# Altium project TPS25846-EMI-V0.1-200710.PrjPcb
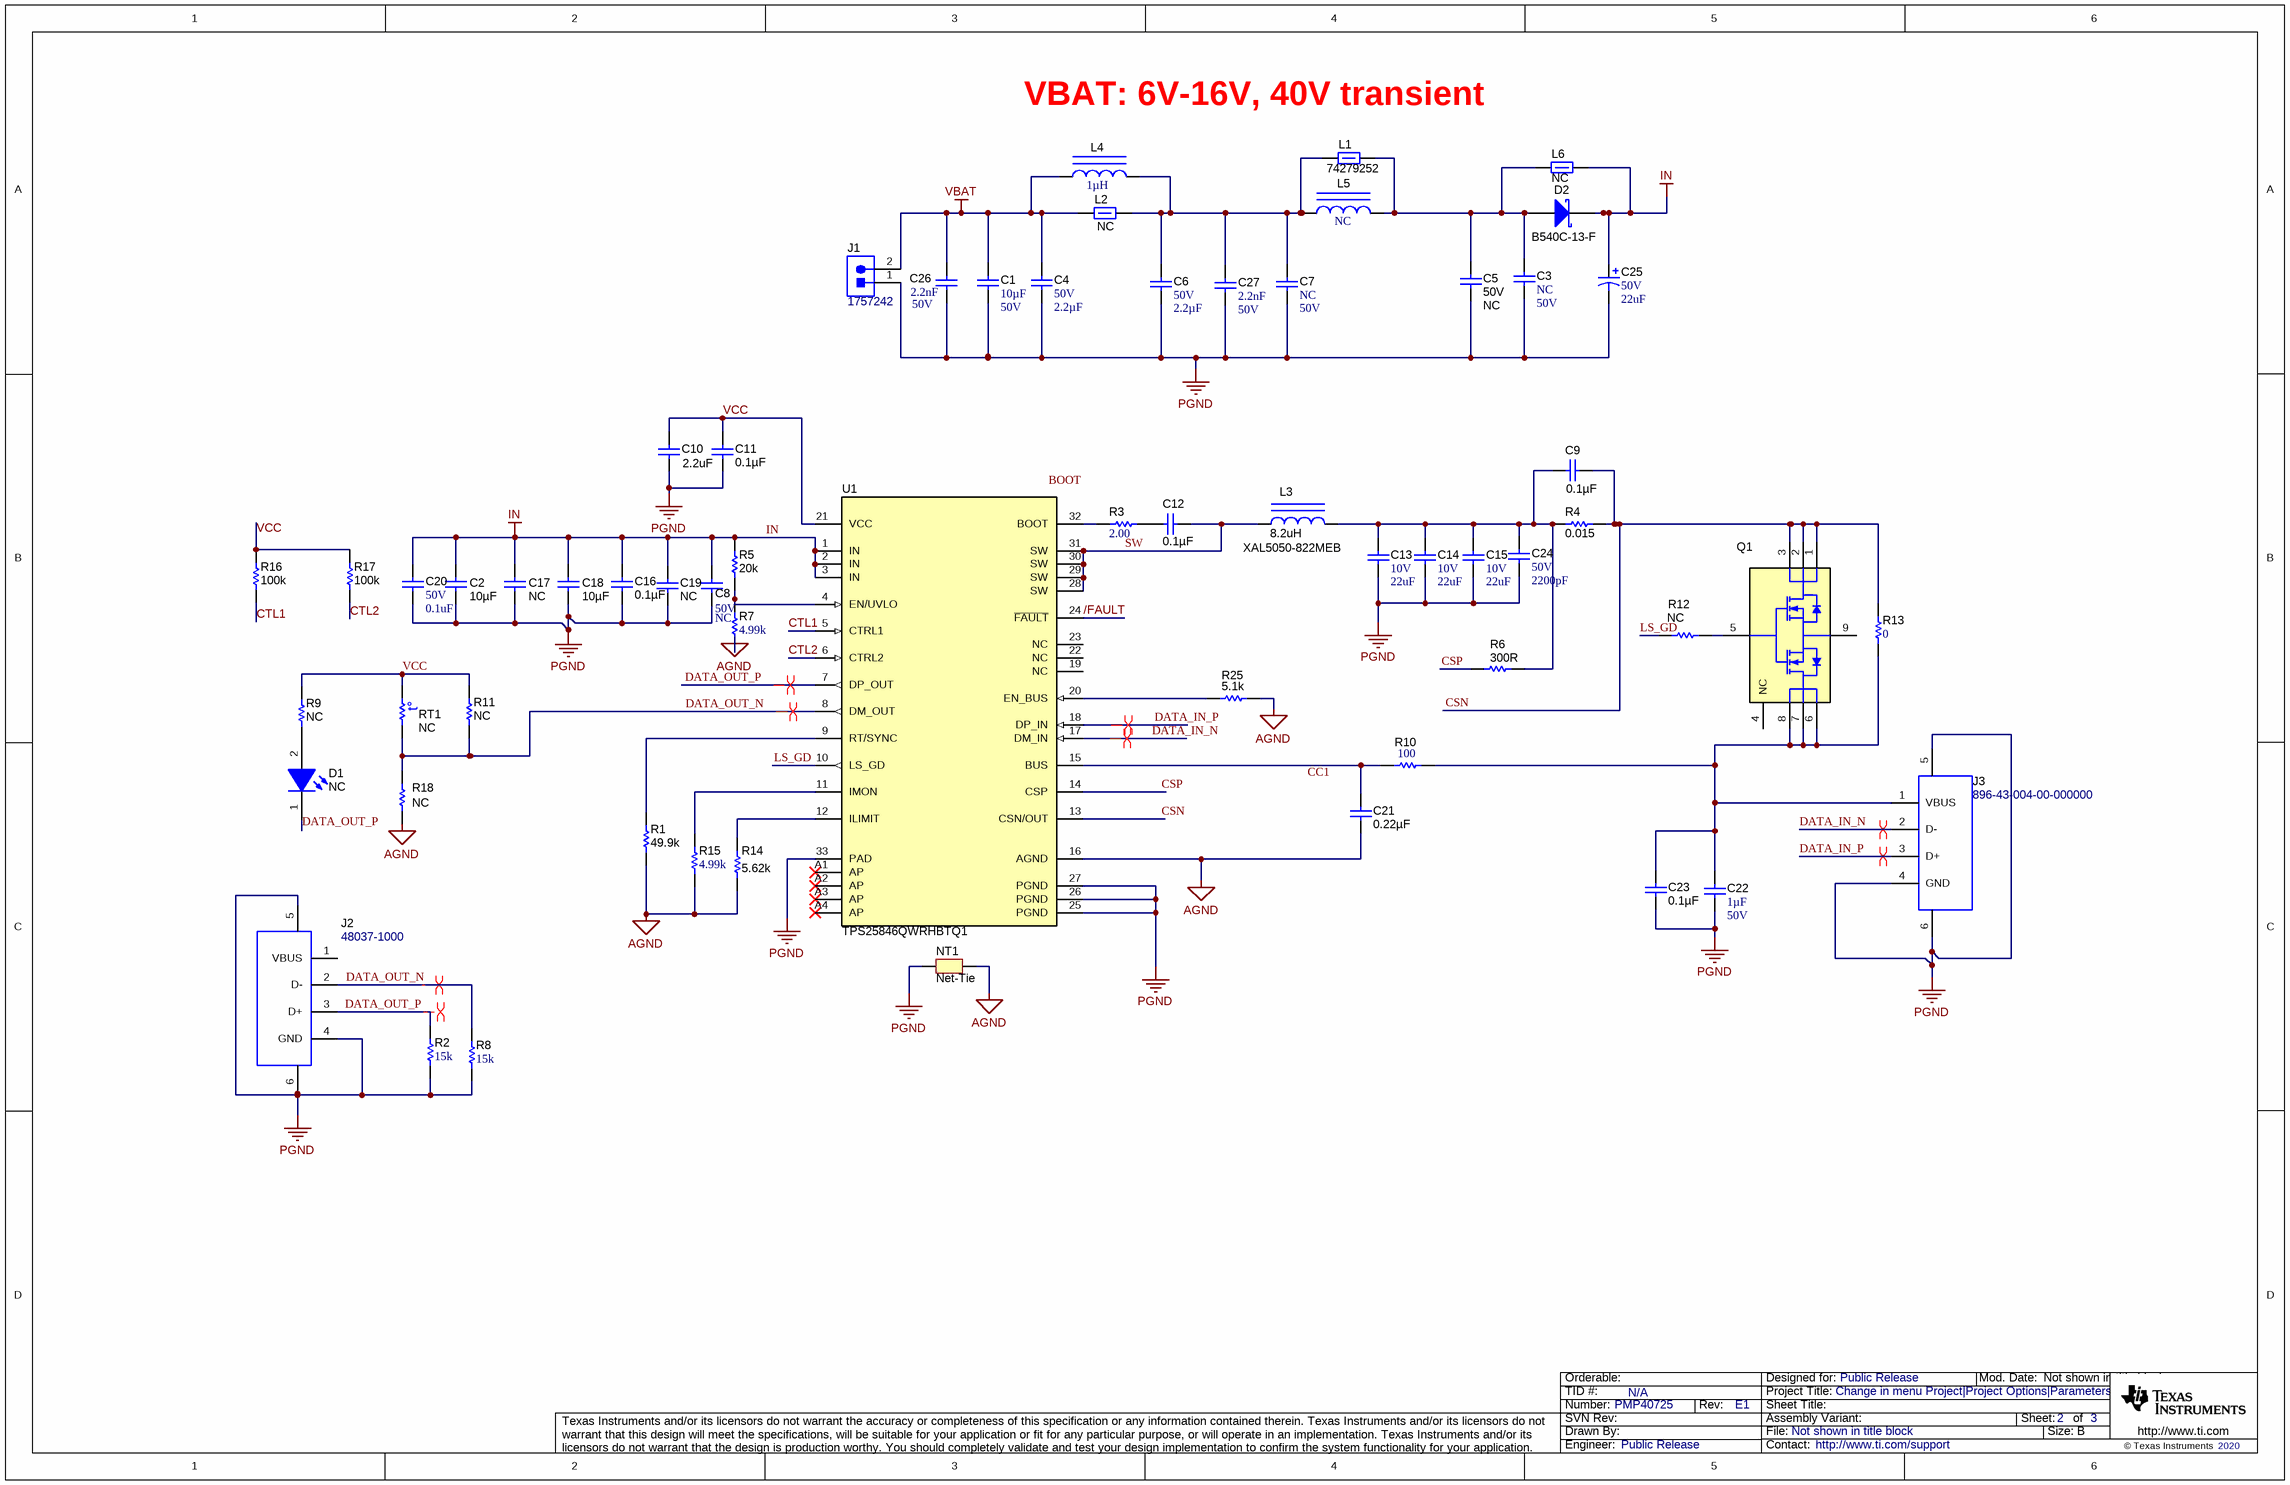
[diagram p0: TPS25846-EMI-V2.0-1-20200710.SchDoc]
TID: N/A; TechSupport: http://www.ti.com/support; SCH_Rev: E1; PRJ_Title: Change in menu Project|Project Options|Parameters; PRJ_Number: PMP40725; PRJ_Engineer: Public Release; PRJ_Customer: Public Release; PCB_Rev: E1; PCB_Layout: Pioneer Li; CopyrightYear: 2020
1 sheet, 61 parts. Net scope: global (net labels, ports and power ports of the same name join across sheets).
Board file: TPS25846-EMI-V2.0-20200503.PcbDoc

## Sheet TPS25846-EMI-V2.0-1-20200710.SchDoc
size 431 x 279 mm; Date: Not shown in title block; ApprovedBy: Not shown in title block; CheckedBy: Not shown in title block; Author: Not shown in title block; CompanyName: Not shown in title block; Engineer: Not shown in title block; Organization: Not shown in title block; Address1: Not shown in title block; Address2: Not shown in title block; Address3: Not shown in title block; Address4: Not shown in title block; DocumentNumber: 2; Revision: Use project parameter SCH_Rev; SheetNumber: 2; SheetTotal: 3; PageSetup: Record=PageOptions¦CenterHorizontal=True¦CenterVertical=True¦PrintScale=1.00¦XCorrection=1.00¦YCorrection=1.00¦PrintKind=0¦BorderSize=5000000¦LeftOffset=0¦BottomOffset=0¦Orientation=2¦PaperLength=1000¦PaperWidth=1000¦Scale=100¦PaperSource=15¦PrintQuality=600¦MediaType=1¦DitherType=10¦PaperKind=Letter¦PrintScaleMode=1

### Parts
C1  ValueDisplayed: 10µF  VDC_V: 50V  [1206_190]  (hidden comment: CGA5L1X7R1H106K160AC)
C2  ValueDisplayed: 10µF  [1210_280]  (hidden comment: UMJ325KB7106MMHP)
C3  Cap_F: NC  VDC_V: 50V  [0603]  (hidden comment: C0603X332K5RACTU)
C4  VDC_V: 50V  ValueDisplayed: 2.2µF  [1206_180]  (hidden comment: UMJ316AB7225KLHT)
C5  VDC_V: 50V  ValueDisplayed: NC  [1206_180L]  (hidden comment: GRM31CR71H475KA12L)
C6  VDC_V: 50V  ValueDisplayed: 2.2µF  [1206_180]  (hidden comment: UMJ316AB7225KLHT)
C7  Cap_F: NC  VDC_V: 50V  [0603]  (hidden comment: C0603X332K5RACTU)
C8  VDC_V: 50V  ValueDisplayed: NC  [0603]  (hidden comment: GRM1885C1H222JA01D)
C9  ValueDisplayed: 0.1µF  [0603]  (hidden comment: C0603C104K5RACAUTO)
C10  ValueDisplayed: 2.2uF  [0603]  (hidden comment: 885012106018)
C11  ValueDisplayed: 0.1µF  [0603]  (hidden comment: C0603C104K5RACAUTO)
C12  ValueDisplayed: 0.1µF  [0603]  (hidden comment: C0603C104K5RACAUTO)
C13  VDC_V: 10V  ValueDisplayed: 22uF  [1206_180]  (hidden comment: GCM31CR71A226KE02)
C14  VDC_V: 10V  ValueDisplayed: 22uF  [1206_180]  (hidden comment: GCM31CR71A226KE02)
C15  VDC_V: 10V  ValueDisplayed: 22uF  [1206_180]  (hidden comment: GCM31CR71A226KE02)
C16  ValueDisplayed: 0.1µF  [0603]  (hidden comment: C0603C104K5RACAUTO)
C17  ValueDisplayed: NC  [1210_280]  (hidden comment: UMJ325KB7106MMHP)
C18  ValueDisplayed: 10µF  [1210_280]  (hidden comment: UMJ325KB7106MMHP)
C19  ValueDisplayed: NC  [0603]  (hidden comment: C0603C104K5RACAUTO)
C20  VDC_V: 50V  ValueDisplayed: 0.1uF  [1206]  (hidden comment: C1206C104M5RACTU)
C21  ValueDisplayed: 0.22µF  [0603]  (hidden comment: CL10B224KO8VPNC)
C22  Cap_F: 1µF  VDC_V: 50V  [0805_HV]  (hidden comment: 08055C105KAT2A)
C23  ValueDisplayed: 0.1µF  [0603]  (hidden comment: C0603C104K5RACAUTO)
C24  VDC_V: 50V  ValueDisplayed: 2200pF  [0603]  (hidden comment: GRM1885C1H222JA01D)
C25  VDC_V: 50V  ValueDisplayed: 22uF  [SM_RADIAL_D]  (hidden comment: EEE-FK1H220P)
C26  Cap_F: 2.2nF  VDC_V: 50V  [0603]  (hidden comment: GRM188R71H222KA01D)
C27  Cap_F: 2.2nF  VDC_V: 50V  [0603]  (hidden comment: GRM188R71H222KA01D)
D1  value NC  [WL-SMCW_RED]  (hidden comment: 150060RS75000)
D2  B540C-13-F  [SMC]
J1  1757242  [PHOENIX_1757242]
J2  48037-1000  [CONN_USB-A-48037-1000]
J3  896-43-004-00-000000  [CONN_USB_896-43-004-00-000000]
L1  74279252  [1812_170_HighSpeed]
L2  NC  [1812_170_HighSpeed]
L3  XAL5050-822MEB  ValueDisplayed: 8.2uH  [XAL5050]
L4  ValueDisplayed: 1µH  [XAL5030]  (hidden comment: XAL5030-102MEB)
L5  ValueDisplayed: NC  [XAL5030]  (hidden comment: XAL5030-102MEB)
L6  NC  [1812_170_HighSpeed]
NT1  Net-Tie  [Net-Tie_10milWide_30milLong]  (net tie, no BOM)
Q1  CSD85312Q3E  [DPA0008A]  (value not drawn)
R1  ValueDisplayed: 49.9k  [0603]  (hidden comment: CRCW060349K9FKEA)
R2  ValueDisplayed: 15k  [0603]  (hidden comment: CRCW060315K0JNEA)
R3  ValueDisplayed: 2.00  [0603]  (hidden comment: MCT06030C2008FP500)
R4  ValueDisplayed: 0.015  [2010]  (hidden comment: WSL2010R0150FEA)
R5  ValueDisplayed: 20k  [0603]  (hidden comment: CRCW060320K0JNEA)
R6  ValueDisplayed: 300R  [0603]  (hidden comment: CRCW0603301RFKEA)
R7  ValueDisplayed: 4.99k  [0603]  (hidden comment: CR0603-FX-4991ELF)
R8  ValueDisplayed: 15k  [0603]  (hidden comment: CRCW060315K0JNEA)
R9  ValueDisplayed: NC  [0603]  (hidden comment: CRCW060310K0JNEA)
R10  ValueDisplayed: 100  [0805_HV]  (hidden comment: ERJ-6GEYJ101V)
R11  ValueDisplayed: NC  [0603]  (hidden comment: CRCW06031K00FKEA)
R12  ValueDisplayed: NC  [0603]  (hidden comment: RMCF0603ZT0R00)
R13  ValueDisplayed: 0  [1206]  (hidden comment: RC1206JR-070RL)
R14  ValueDisplayed: 5.62k  [0603]  (hidden comment: CRCW06035K62FKEA)
R15  ValueDisplayed: 4.99k  [0603]  (hidden comment: CR0603-FX-4991ELF)
R16  ValueDisplayed: 100k  [0603]  (hidden comment: CRCW0603100KFKEA)
R17  ValueDisplayed: 100k  [0603]  (hidden comment: CRCW0603100KFKEA)
R18  ValueDisplayed: NC  [0603]  (hidden comment: CRCW060339K2FKEA)
R25  ValueDisplayed: 5.1k  [0603]  (hidden comment: CRCW06035K10JNEA)
RT1  value NC  [0603S]  (hidden comment: NCP18WM474J03RB)
U1  PartNumber: TPS25846QWRHBTQ1  [RHB0032R]  (hidden comment: TPS25840QWRHBTQ1)

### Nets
AGND: C21.2 NT1.2 R1.1 R7.1 R14.1 R15.2 R18.1 R25.1 U1.16(AGND)
IN: C2.1 C8.1 C16.1 C17.1 C18.1 C19.1 C20.1 C25.1(+) D2.1(K) L6.2 R5.2 U1.1(IN) U1.2(IN) U1.3(IN)
PGND: C1.2 C2.2 C3.2 C4.2 C5.2 C6.2 C7.2 C8.2 C10.2 C11.2 C13.2 C14.2 C15.2 C16.2 C17.2 C18.2 C19.2 C20.2 C22.2 C23.2 C24.2 C25.2(-) C26.2 C27.2 J1.1 J2.4(GND) J2.5(Shield) J2.6(Shield) J3.4(GND) J3.5(Shield) J3.6(Shield) NT1.1 R2.1 R8.1 U1.25(PGND) U1.26(PGND) U1.27(PGND) U1.33(PAD)
VBAT: C1.1 C4.1 C26.1 J1.2 L2.1 L4.1
/FAULT: U1.24(~{FAULT})
CSN: C9.1 Q1.1(D1) Q1.2(D2) Q1.3(D3) R4.2 R13.2 U1.13(CSN/OUT)
CSP: R6.1 U1.14(CSP)
CTL1: R16.1 U1.5(CTRL1)
CTL2: R17.1 U1.6(CTRL2)
DATA_IN_N: J3.2(D-) U1.17(DM_IN)
DATA_IN_P: J3.3(D+) U1.18(DP_IN)
DATA_OUT_N: J2.2(D-) R8.2 R11.1 R18.2 RT1.1 U1.8(DM_OUT)
DATA_OUT_P: D1.1(K) J2.3(D+) R2.2 U1.7(DP_OUT)
LS_GD: R12.1 U1.10(LS_GD)
SW: C12.2 L3.1 U1.28(SW) U1.29(SW) U1.30(SW) U1.31(SW)
VCC: C10.1 C11.1 R9.2 R11.2 R16.2 R17.2 RT1.2 U1.21(VCC)
NetC3_1: C3.1 C5.1 D2.2(A) L1.2 L5.2 L6.1
NetC6_1: C6.1 C7.1 C27.1 L1.1 L2.2 L4.2 L5.1
NetC9_2: C9.2 C13.1 C14.1 C15.1 C24.1 L3.2 R4.1 R6.2
NetC12_1: C12.1 R3.2
NetC21_1: C21.1 R10.1 U1.15(BUS)
NetC22_1: C22.1 C23.1 J3.1(VBUS) Q1.6(D2) Q1.7(D3) Q1.8(D4) R10.2 R13.1
NetD1_2: D1.2(A) R9.1
NetQ1_5: Q1.5(G) R12.2
NetR1_2: R1.2 U1.9(RT/SYNC)
NetR3_1: R3.1 U1.32(BOOT)
NetR5_1: R5.1 R7.2 U1.4(EN/UVLO)
NetR14_2: R14.2 U1.12(ILIMIT)
NetR15_1: R15.1 U1.11(IMON)
NetR25_2: R25.2 U1.20(EN_BUS)

Not connected (* = marked no-connect by the designer): J2 1(VBUS); Q1 4(NC) 9(S); U1 19(NC) 22(NC) 23(NC) A1(AP)* A2(AP)* A3(AP)* A4(AP)*

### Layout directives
differential pair: DATA_IN_N, DATA_IN_P, DATA_OUT_N, DATA_OUT_P

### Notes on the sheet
- VBAT: 6V-16V, 40V transient
- Labels drawn without touching a wire or pin: BOOT, CC1

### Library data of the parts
C1 = CMP-0085950-1: CAP, CERM, 10 µF, 50 V,+/- 10%, X7R, AEC-Q200 Grade 1, 1206; Manufacturer: TDK; SizeZ_mm: 1.9; Value: 10uF; Cap_Case: 1206; AEC Grade: 1; TaMin_C: -55°C; U/M: EA; SizeArea_mm2: 5.12; TaMax_C: 125°C; AEC Qualified: Y; AEC Category: Q200; SizeX_mm: 3.2; SizeY_mm: 1.6; Polarized: N; SizeAreaWB_mm2: 10.92
C2 C18 = CMP-0082302-1: CAP, CERM, 10 µF, 50 V,+/- 20%, X7R, AEC-Q200 Grade 1, 1210; Manufacturer: Taiyo Yuden; SizeAreaWB_mm2: 14.7; SizeArea_mm2: 8; AEC Qualified: Y; AEC Category: Q200; Value: 10uF; TaMax_C: 125°C; SizeZ_mm: 2.8; AEC Grade: 1; Polarized: N; TaMin_C: -55°C; VDC_V: 50V; SizeY_mm: 2.5; U/M: EA; CompType: Capacitor; SizeX_mm: 3.2; Cap_Case: 1210
C3 C7 = CMP-0006985-4: CAP, CERM, 3300 pF, 50 V, +/- 10%, X7R, 0603; Manufacturer: Kemet; TaMin_C: -55°C; Polarized: N; SizeAreaWB_mm2: 4.68; Value1: Unknown; U/M: EA; Value: 3300pF; TaMax_C: 125°C; SizeZ_mm: 1; SizeX_mm: 1.6; SizeY_mm: 0.8; SizeArea_mm2: 1.28; AEC Category: Q200
C4 C6 = CMP-0080745-1: CAP, CERM, 2.2 µF, 50 V,+/- 10%, X7R, AEC-Q200 Grade 1, 1206; Manufacturer: Taiyo Yuden; SizeAreaWB_mm2: 10.92; SizeArea_mm2: 5.12; AEC Qualified: Y; AEC Category: Q200; Value: 2.2uF; TaMax_C: 125°C; SizeZ_mm: 1.8; AEC Grade: 1; Polarized: N; TaMin_C: -55°C; SizeY_mm: 1.6; U/M: EA; SizeX_mm: 3.2; Cap_Case: 1206
C5 = CMP-0008969-2: CAP, CERM, 4.7 uF, 50 V, +/- 10%, X7R, 1206; Manufacturer: MuRata; TaMin_C: -55°C; Polarized: N; SizeAreaWB_mm2: 10.92; Value1: Unknown; U/M: EA; Value: 4.7uF; TaMax_C: 125°C; SizeZ_mm: 1.8; SizeX_mm: 3.2; SizeY_mm: 1.6; Cap_Case: 2220; SizeArea_mm2: 5.12; CompType: Capacitor; Cap_F: 4.7µF; AEC Category: Q200
C8 C24 = CMP-0007198-4: CAP, CERM, 2200 pF, 50 V, +/- 5%, C0G/NP0, 0603; Manufacturer: MuRata; TaMin_C: -55°C; Polarized: N; SizeAreaWB_mm2: 4.68; Value1: Unknown; U/M: EA; Value: 2200pF; TaMax_C: 125°C; SizeZ_mm: 1; SizeX_mm: 1.6; SizeY_mm: 0.8; SizeArea_mm2: 1.28; Cap_F: 2.2nF; AEC Category: Q200
C9 C11 C12 C16 C19 C23 = CMP-0079602-1: CAP, CERM, 0.1 µF, 50 V,+/- 10%, X7R, AEC-Q200 Grade 1, 0603; Manufacturer: Kemet; TaMin_C: -55°C; Polarized: N; SizeAreaWB_mm2: 4.68; U/M: EA; Value: 0.1uF; TaMax_C: 125°C; SizeZ_mm: 1; SizeX_mm: 1.6; SizeY_mm: 0.8; Value2: 50V; SizeArea_mm2: 1.28; CompType: Capacitor; AEC Qualified: Y; Cap_F: 100nF; AEC Category: Q200
C10 = CMP-0006825-5: CAP, CERM, 2.2 uF, 16 V, +/- 20%, X5R, 0603; Manufacturer: Wurth Elektronik; TaMin_C: -55°C; Polarized: N; SizeAreaWB_mm2: 4.68; Value1: Unknown; U/M: EA; Value: 2.2uF; TaMax_C: 85°C; SizeZ_mm: 1; SizeX_mm: 1.6; SizeY_mm: 0.8; Value2: 16V; SizeArea_mm2: 1.28; CompType: Capacitor; Cap_F: 2.2µF; AEC Category: Q200
C13-C15 = CMP-0008811-2: CAP, CERM, 22 uF, 10 V, +/- 10%, X7R, AEC-Q200 Grade 1, 1206; Manufacturer: MuRata; TaMin_C: -55°C; Polarized: N; SizeAreaWB_mm2: 10.92; Value1: Unknown; U/M: EA; Value: 22uF; TaMax_C: 125°C; SizeZ_mm: 1.8; SizeX_mm: 3.2; SizeY_mm: 1.6; Cap_Case: 1206; SizeArea_mm2: 5.12; AEC Qualified: Y; Cap_F: 22µF; AEC Grade: 1; AEC Category: Q200
C17 = CMP-0082302-1: CAP, CERM, 10 µF, 50 V,+/- 20%, X7R, AEC-Q200 Grade 1, 1210; Manufacturer: Taiyo Yuden; Cap_F: 10µF; SizeAreaWB_mm2: 14.7; SizeArea_mm2: 8; AEC Qualified: Y; AEC Category: Q200; Value: 10uF; TaMax_C: 125°C; SizeZ_mm: 2.8; AEC Grade: 1; Polarized: N; TaMin_C: -55°C; VDC_V: 50V; SizeY_mm: 2.5; U/M: EA; CompType: Capacitor; SizeX_mm: 3.2; Cap_Case: 1210
C20 = CMP-0008587-2: CAP, CERM, 0.1 uF, 50 V, +/- 20%, X7R, 1206; Manufacturer: Kemet; TaMin_C: -55°C; ESR_ohm: 0.059; Polarized: N; SizeAreaWB_mm2: 10.92; Value1: 0.059 ohm; U/M: EA; Value: 0.1uF; TaMax_C: 125°C; SizeZ_mm: 1.35; SizeX_mm: 3.2; SizeY_mm: 1.6; SizeArea_mm2: 5.12; Cap_F: 100nF; IRMS_A: 1.2A; AEC Category: Q200
C21 = CMP-0080102-1: CAP, CERM, 0.22 µF, 16 V,+/- 10%, X7R, AEC-Q200 Grade 1, 0603; Manufacturer: Samsung; Cap_F: 220nF; SizeAreaWB_mm2: 4.68; SizeArea_mm2: 1.28; AEC Qualified: Y; AEC Category: Q200; Value: 0.22uF; TaMax_C: 125°C; SizeZ_mm: 1; Polarized: N; TaMin_C: -55°C; VDC_V: 16V; SizeY_mm: 0.8; U/M: EA; CompType: Capacitor; SizeX_mm: 1.6
C22 = CMP-0007634-2: CAP, CERM, 1 uF, 50 V, +/- 10%, X7R, 0805; Manufacturer: AVX; TaMin_C: -55°C; Polarized: N; SizeAreaWB_mm2: 6.75; Value1: Unknown; U/M: EA; Value: 1uF; TaMax_C: 125°C; SizeZ_mm: 1.45; SizeX_mm: 2; SizeY_mm: 1.25; Cap_Case: 0805; SizeArea_mm2: 2.5; AEC Category: Q200
C25 = CMP-0011179-2: CAP, AL, 22 uF, 50 V, +/- 20%, 0.88 ohm, AEC-Q200 Grade 2, SMD; Manufacturer: Panasonic; TaMin_C: -55°C; ESR_ohm: 0.88; Polarized: Y; SizeAreaWB_mm2: 84.28; U/M: EA; Value: 22uF; TaMax_C: 105°C; SizeZ_mm: 5.4; SizeX_mm: 7.8; SizeY_mm: 6.6; Cap_Case: D; SizeArea_mm2: 51.48; CompType: Capacitor; Cap_F: 22µF; IRMS_A: 165mA; AEC Grade: 2; AEC Category: Q200
C26 C27 = CMP-0007443-4: CAP, CERM, 2200 pF, 50 V, +/- 10%, X7R, 0603; Manufacturer: MuRata; TaMin_C: -55°C; Polarized: N; SizeAreaWB_mm2: 4.68; Value1: Unknown; U/M: EA; Value: 2200pF; TaMax_C: 125°C; SizeZ_mm: 1; SizeX_mm: 1.6; SizeY_mm: 0.8; SizeArea_mm2: 1.28; AEC Category: Q200
D1 = CMP-0002947-2: LED, Red, SMD; Manufacturer: Wurth Elektronik; Io_A: 30mA; Power_TotalModule: 72mW; Vr_V: 5V; Tjmax_C: 85°C; Value1: 0.072W; U/M: EA; Angle: 140; Vf_V: 2V; Type: AlInGaP
D2 = CMP-0028431-1: Diode, Schottky, 40 V, 5 A, SMC; Manufacturer: Diodes Inc.; Io_A: 5A; Green_Lifecycle: Active; SizeAreaWB_mm2: 83.2686; Vr_V: 40V; Green_REACh: Passed; TJmax_C: 125°C; U/M: EA; Value: 40V; SizeZ_mm: 2.6; SizeX_mm: 8.13; SizeY_mm: 6.22; Vf_V: 5.5dV; Value2: 0.55V; SizeArea_mm2: 50.5686; AEC Category: Q101; RJC_CperW: 10
J1 = CMP-0055534-1: Header (Shrouded), 5.08 mm, 2x1, Tin, R/A, TH; Manufacturer: Phoenix Contact; CT: FALSE
J2 = CMP-0055294-1: Connector, Plug, USB Type A, R/A, Top Mount SMT; Manufacturer: Molex; CNHeader: FALSE; Green_Lifecycle: Active; Gender: Male; Green_REACh: Passed; CT: TRUE
J3 = CMP-0055109-1: Connector, Receptacle, USB TYPE A, R/A, Top Mount SMT; Manufacturer: Mill-Max; Cert_VDE: N; CNHeader: FALSE; Current_A: 1A; Green_Lifecycle: Not Set; Gender: Female; Green_REACh: Incomplete; Voltage_V: 30V; Row_Count: 1; Pitch_mm: 2; ContactFinish: Gold; CT: TRUE
L1 = CMP-0003170-1: Ferrite Bead, 880 ohm @ 100 MHz, 4 A, 1812; Manufacturer: Wurth Elektronik; Ztyp@1GHz_Ohm: 80.561; ZTyp@100MHz_Ohm: 880; SizeAreaWB_mm2: 23.1; DCR_ohm: 0.035; Value1: 0.035 ohm; Value: 880 ohm; Imax_A: 4A; SizeZ_mm: 1.7; SizeX_mm: 4.5; SizeY_mm: 3.2; SizeArea_mm2: 14.4
L2 L6 = CMP-0003170-1: Ferrite Bead, 880 ohm @ 100 MHz, 4 A, 1812; Manufacturer: Wurth Elektronik; PartNumber: 74279252; Ztyp@1GHz_Ohm: 80.561; ZTyp@100MHz_Ohm: 880; SizeAreaWB_mm2: 23.1; DCR_ohm: 0.035; Value1: 0.035 ohm; Value: 880 ohm; Imax_A: 4A; SizeZ_mm: 1.7; SizeX_mm: 4.5; SizeY_mm: 3.2; SizeArea_mm2: 14.4
L3 = CMP-0061010-1: Inductor, Shielded, Composite, 8.2 uH, 5.6 A, 0.03 ohm, SMD; Manufacturer: Coilcraft; Isat: 5.6A @ 30% inductance drop; Irms: 6.1A @ 40C rise; Green_Lifecycle: Not Set; SizeAreaWB_mm2: 54.4544; DCR_ohm: 0.03; Green_REACh: Incomplete; Value: 8.2uH; Imax_A: 5.6A; SizeZ_mm: 5.1; SizeX_mm: 5.28; SizeY_mm: 5.48; SizeArea_mm2: 28.9344; Ind_H: 8.2µH; AEC Category: Q200
L4 = CMP-0082088-1: Inductor, Shielded, CAPPR7.5-16X20, 1 µH, 11.1 A, 0.0094 ohm, AEC-Q200 Grade 1, SMD; Manufacturer: Coilcraft; Isat: 14A @ 30% inductance drop; Irms: 11.1A @ 40C rise; SizeAreaWB_mm2: 54.4544; DCR_ohm: 9.4m; Value: 1uH; Imax_A: 11.1A; SizeZ_mm: 3.1; SizeX_mm: 5.28; SizeY_mm: 5.48; SizeArea_mm2: 28.9344; AEC Qualified: Y; AEC Grade: 1; AEC Category: Q200
L5 = CMP-0082088-1: Inductor, Shielded, CAPPR7.5-16X20, 1 µH, 11.1 A, 0.0094 ohm, AEC-Q200 Grade 1, SMD; Manufacturer: Coilcraft; Isat: 14A @ 30% inductance drop; Irms: 11.1A @ 40C rise; SizeAreaWB_mm2: 54.4544; DCR_ohm: 9.4m; Value: 1uH; Imax_A: 11.1A; SizeZ_mm: 3.1; SizeX_mm: 5.28; SizeY_mm: 5.48; SizeArea_mm2: 28.9344; Ind_H: 1µH; AEC Qualified: Y; AEC Grade: 1; AEC Category: Q200
NT1 = CMP-0078142-2: Single point connection between nets.
Q1 = CMP-0000210-1: MOSFET, 2-CH, N-CH, 20 V, 12 A, DPA0008A (VSON-8); Alternate Manufacturer: None; Manufacturer: Texas Instruments; SizeZ_mm: 1; ChType: N; Value2: 11.7 nC; Value1: 0.01; VdsMax_V: 20V; SizeX_mm: 3.3; Vgs_V: 10V; Value: 20V; Rdson45_ohm: 0.014; SizeArea_mm2: 10.89; AEC Category: Q101; IdsMax_A: 12A; SizeAreaWB_mm2: 18.49; U/M: EA; QgTyp_nC: 11.7
R1 = CMP-0022447-4: RES, 49.9 k, 1%, 0.1 W, AEC-Q200 Grade 0, 0603; Manufacturer: Vishay-Dale; Power_W: 100mW; TempCo: 100 ppm/C; Value_Code: 49k9; Value: 49.9k; EIA_Code: E96; SizeX_mm: 1.6; SizeY_mm: 0.8; SizeZ_mm: 1; Value2: 0.1W; SizeArea_mm2: 1.28; CompType: Resistor; AEC Qualified: Y; VDC_V: 75V; AEC Category: Q200; AEC Grade: 0
R2 R8 = CMP-0025719-4: RES, 15 k, 5%, 0.1 W, AEC-Q200 Grade 0, 0603; Manufacturer: Vishay-Dale; Power_W: 100mW; TempCo: 200 ppm/C; Value_Code: 15k0; Value: 15k; EIA_Code: E24; SizeX_mm: 1.6; SizeY_mm: 0.8; SizeZ_mm: 1; Value2: 0.1W; SizeArea_mm2: 1.28; AEC Qualified: Y; VDC_V: 75V; AEC Category: Q200; AEC Grade: 0
R3 = CMP-0022732-2: RES, 2.00, 1%, 0.125 W, 0603; Manufacturer: Vishay/Beyschlag; Power_W: 125mW; TempCo: 50 ppm/C; Value_Code: 2R00; U/M: EA; Value: 2.00; EIA_Code: E96; Res_ohm: 2; SizeX_mm: 1.6; SizeY_mm: 0.8; Value2: 0.125W; SizeArea_mm2: 1.28; AEC Qualified: N; AEC Category: Q200; SizeZ_mm: 1
R4 = CMP-0016558-2: RES, 0.015, 1%, 0.5 W, 2010; Manufacturer: Vishay-Dale; Power_W: 500mW; TempCo: 75 ppm/C; Value_Code: R015; U/M: EA; Value: 0.015; EIA_Code: E96; SizeX_mm: 5; SizeY_mm: 2.5; SizeZ_mm: 1.66; Value2: 0.5W; SizeArea_mm2: 12.5; CompType: Resistor; AEC Category: Q200
R5 = CMP-0025753-4: RES, 20 k, 5%, 0.1 W, AEC-Q200 Grade 0, 0603; Manufacturer: Vishay-Dale; Power_W: 100mW; TempCo: 200 ppm/C; Value_Code: 20k0; Value: 20k; EIA_Code: E24; SizeX_mm: 1.6; SizeY_mm: 0.8; SizeZ_mm: 1; Value2: 0.1W; SizeArea_mm2: 1.28; CompType: Resistor; AEC Qualified: Y; VDC_V: 75V; AEC Category: Q200; AEC Grade: 0
R6 = CMP-0022321-5: RES, 301, 1%, 0.1 W, AEC-Q200 Grade 0, 0603; Manufacturer: Vishay-Dale; Power_W: 100mW; TempCo: 100 ppm/C; Value_Code: 301R; Value: 301; EIA_Code: E96; SizeX_mm: 1.6; SizeY_mm: 0.8; SizeZ_mm: 1; Value2: 0.1W; SizeArea_mm2: 1.28; CompType: Resistor; AEC Qualified: Y; VDC_V: 75V; AEC Category: Q200; AEC Grade: 0
R7 R15 = CMP-0021989-3: RES, 4.99 k, 1%, 0.1 W, 0603; Manufacturer: Bourns; Power_W: 100mW; TempCo: 100 ppm/C; Value_Code: 4k99; U/M: EA; Value: 4.99k; EIA_Code: E96; SizeX_mm: 1.6; SizeY_mm: 0.8; SizeZ_mm: 1; Value2: 0.1W; SizeArea_mm2: 1.28; AEC Category: Q200
R9 = CMP-0025701-4: RES, 10 k, 5%, 0.1 W, AEC-Q200 Grade 0, 0603; Manufacturer: Vishay-Dale; Power_W: 100mW; TempCo: 200 ppm/C; Value_Code: 10k0; Value: 10k; EIA_Code: E24; SizeX_mm: 1.6; SizeY_mm: 0.8; SizeZ_mm: 1; Value2: 0.1W; SizeArea_mm2: 1.28; CompType: Resistor; AEC Qualified: Y; VDC_V: 75V; AEC Category: Q200; AEC Grade: 0
R10 = CMP-0020618-3: RES, 100, 5%, 0.125 W, AEC-Q200 Grade 0, 0805; Manufacturer: Panasonic; Power_W: 125mW; TempCo: 200 ppm/C; Value_Code: 100R; Value: 100; EIA_Code: E24; SizeX_mm: 2; SizeY_mm: 1.25; SizeZ_mm: 1.45; Value2: 0.125W; SizeArea_mm2: 2.5; AEC Qualified: Y; VDC_V: 150V; AEC Category: Q200; AEC Grade: 0; SizeAreaWB_mm2: 6.75
R11 = CMP-0022109-5: RES, 1.00 k, 1%, 0.1 W, AEC-Q200 Grade 0, 0603; Manufacturer: Vishay-Dale; Power_W: 100mW; TempCo: 100 ppm/C; Value_Code: 1k00; Value: 1.00k; EIA_Code: E96; Res_ohm: 1k; SizeX_mm: 1.6; SizeY_mm: 0.8; SizeZ_mm: 1; Value2: 0.1W; SizeArea_mm2: 1.28; CompType: Resistor; AEC Qualified: Y; VDC_V: 75V; AEC Category: Q200; AEC Grade: 0
R12 = CMP-0023343-3: RES, 0, 1%, 0.1 W, AEC-Q200 Grade 0, 0603; Manufacturer: Stackpole Electronics Inc; Power_W: 100mW; TempCo: ppm/C; Value_Code: 0; U/M: EA; Value: 0; SizeX_mm: 1.6; SizeY_mm: 0.8; SizeZ_mm: 1; Value2: 0.1W; SizeArea_mm2: 1.28; CompType: Resistor; AEC Qualified: Y; AEC Category: Q200
R13 = CMP-0018759-2: RES, 0, 5%, 0.25 W, 1206; Manufacturer: Yageo America; Power_W: 250mW; TempCo: 200 ppm/C; Value_Code: 0000; U/M: EA; Value: 0; EIA_Code: E24; SizeX_mm: 3.2; SizeY_mm: 1.6; SizeZ_mm: 1.35; Value2: 0.25W; SizeArea_mm2: 5.12; VDC_V: 200V; AEC Category: Q200
R14 = CMP-0022513-4: RES, 5.62 k, 1%, 0.1 W, AEC-Q200 Grade 0, 0603; Manufacturer: Vishay-Dale; Power_W: 100mW; TempCo: 100 ppm/C; Value_Code: 5k62; Value: 5.62k; EIA_Code: E96; SizeX_mm: 1.6; SizeY_mm: 0.8; SizeZ_mm: 1; Value2: 0.1W; SizeArea_mm2: 1.28; CompType: Resistor; AEC Qualified: Y; VDC_V: 75V; AEC Category: Q200; AEC Grade: 0
R16 R17 = CMP-0021990-4: RES, 100 k, 1%, 0.1 W, AEC-Q200 Grade 0, 0603; Manufacturer: Vishay-Dale; Power_W: 100mW; TempCo: 100 ppm/C; Value: 100k; EIA_Code: E96; SizeX_mm: 1.6; SizeY_mm: 0.8; SizeZ_mm: 1; Value2: 0.1W; SizeArea_mm2: 1.28; CompType: Resistor; AEC Qualified: Y; VDC_V: 75V; AEC Category: Q200; AEC Grade: 0
R18 = CMP-0022369-4: RES, 39.2 k, 1%, 0.1 W, AEC-Q200 Grade 0, 0603; Manufacturer: Vishay-Dale; Power_W: 100mW; TempCo: 100 ppm/C; Value_Code: 39k2; Value: 39.2k; EIA_Code: E96; SizeX_mm: 1.6; SizeY_mm: 0.8; SizeZ_mm: 1; Value2: 0.1W; SizeArea_mm2: 1.28; CompType: Resistor; AEC Qualified: Y; VDC_V: 75V; AEC Category: Q200; AEC Grade: 0
R25 = CMP-0025830-4: RES, 5.1 k, 5%, 0.1 W, AEC-Q200 Grade 0, 0603; Manufacturer: Vishay-Dale; Power_W: 100mW; TempCo: 200 ppm/C; Value_Code: 5k10; Value: 5.1k; EIA_Code: E24; SizeX_mm: 1.6; SizeY_mm: 0.8; SizeZ_mm: 1; Value2: 0.1W; SizeArea_mm2: 1.28; CompType: Resistor; AEC Qualified: Y; VDC_V: 75V; AEC Category: Q200; AEC Grade: 0
RT1 = CMP-0002545-3: Thermistor NTC, 470k ohm, 5%, 0603; Manufacturer: MuRata; TaMax_C: 125°C; SizeX_mm: 1.6; SizeY_mm: 0.8; TaMin_C: -40°C; Power_W: 100mW; SizeZ_mm: 1; SizeArea_mm2: 1.28; SizeAreaWB_mm2: 4.68; U/M: EA
U1 = CMP-0082640-2: USB Type-A BC1.2 5-V 3.5-A Output, 36-V Input Synchronous Buck With Cable Compensation, RHB0032R (VQFN-32); Manufacturer: Texas Instruments; SizeAreaWB_mm2: 49; SizeArea_mm2: 25; AEC Qualified: Y; AEC Category: Q200; SizeZ_mm: 1; SizeY_mm: 5; CompType: IC; Rating: Automotive

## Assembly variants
001: not fitted FID1 FID2 FID3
